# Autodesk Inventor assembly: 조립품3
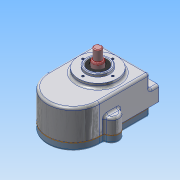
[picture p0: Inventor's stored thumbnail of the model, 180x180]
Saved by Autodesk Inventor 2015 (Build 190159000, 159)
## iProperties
Created: 2024-03
Part Number: 조립품3
Document SubType Name: Assembly
Designer: 학생용
Author: 학생용
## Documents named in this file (9)
- C:\Users\학생용\Desktop\김산\조립품3.iam
- C:\Users\학생용\Desktop\김산\부품2.ipt
- C:\Users\학생용\Desktop\740304V1017\오일레스 부시.ipt
- C:\Users\학생용\Desktop\740304V1017\구동기어.ipt
- C:\Users\학생용\Desktop\740304V1017\오일 실 14 25 7.ipt
- C:\Users\학생용\Desktop\740304V1017\스퍼기어.ipt
- C:\Users\학생용\Desktop\740304V1017\커버.ipt
- C:\Users\학생용\Desktop\740304V1017\육각 소켓 머리 볼트 M5x12.ipt
- C:\Users\학생용\Desktop\740304V1017\가스켓.ipt
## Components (2 placed, 2 different names)
1. 구동기어:1
2. 가스켓:1 — 플러쉬:1
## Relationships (1: Flush 1)
- 플러쉬:1 [Flush]: 가스켓:1
